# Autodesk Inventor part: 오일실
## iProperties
Created: 2009-02
Part Number: 오일실
Material: 고무
Description: 오일-실
Document SubType Name: Modeling
Standard: KS B 2804
Designer: KYOUNG IL JANG
Standards Organization: KS
Language: ko-KR
Size Designation: D - 10 20 7
Categories: <MemberInstance><Categories><Category DisplayName="샤프트 부품" InternalName="7f7aeb1f-a693-4053-b835-cee3144e0d98" Mnemonic="SHFT"><Category DisplayName="실링" Intern
Density: 0.93 g/cm^3
Mass: 1.11329 g
Surface Area: 16.3871 cm^2
Volume: 1.19708 cm^3
Company: 한국ATC센터
IsCustomPart: 0
Author: KYOUNG IL JANG
